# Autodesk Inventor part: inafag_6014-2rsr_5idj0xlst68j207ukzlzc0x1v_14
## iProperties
Shininess: 64.0
Angle Display Precision: 2
Document Length Units: 11269
Document Angle Units: 11279
Document Time Units: 11290
Document Mass Units: 11283
Document Length Units Precision: 3
Document Angle Units Precision: 2
Compacted: True
Created: 2008-08
Part Number: inafag_6014-2rsr_5idj0xlst68j207ukzlzc0x1v_14
Document SubType Name: Modeling
Designer: tpomodeler
Density: 0.0
Volumn: 0.0
Area: 0.0
PropertySet Name: Model Information
Control State: 0
Master: False
Checked Out: False
Author: tpomodeler
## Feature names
1. inafag_6014-2rsr_5idj0xlst68j207ukzlzc0x1v
